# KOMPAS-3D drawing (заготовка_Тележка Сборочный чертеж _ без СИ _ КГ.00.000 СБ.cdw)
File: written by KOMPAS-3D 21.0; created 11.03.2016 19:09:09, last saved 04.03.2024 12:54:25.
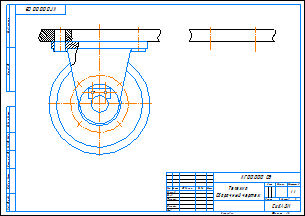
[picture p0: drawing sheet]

Sheet 1: A3, landscape

Document properties: Автор: Alexey; Полное имя файла: C:\Users\study\Desktop\! Разработка сборочных чертежей и спец\Тележка СБ\заготовка_Тележка Сборочный чертеж _ без СИ _ КГ.00.000 СБ.cdw

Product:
- Part/product: (unnamed)
  - Component: Болт М14x55 ГОСТ 15591-70  | pos. 1  | Масса: 0.0827; Раздел спецификации: Стандартные изделия
  - Component: Шайба 14Л ГОСТ 6402-70  | pos. 1  | Масса: 0.005487; Раздел спецификации: Стандартные изделия
  - Component: Гайка М14-6H(S21) ГОСТ 5915-70  | qty 2  | pos. 1  | Масса: 0.02533; Раздел спецификации: Стандартные изделия

Title block, sheet 1: Наименование: Тележка / Сборочный чертеж; scale: 1:1; Количество листов документа: 1; organisation: СибАДИ; Форматы листов документа: A3; stored path: C:\Users\Alexey\Desktop\СБ спец\Колесо Сборочный чертеж _ КГ.00.000 СБ.cdw

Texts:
  Крепежное изделие ГОСТ
  Болт
  ГОСТ
  Шайба
  Гайка
  Шайба 14Л ГОСТ 6402-70
  Болт М14x55 ГОСТ 15591-70
  Гайка М14-6H(S21) ГОСТ 5915-70
Dimensions and other numbers on the sheet: 6; 5; 58; 40Х; 019; 1; 37; 2; 1:1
